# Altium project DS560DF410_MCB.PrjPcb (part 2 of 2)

## Sheet DF410_Egress_3.SchDoc: Retimer Egress RX1-4
size A2; Date: Not shown in title block; ApprovedBy: Not shown in title block; CheckedBy: Not shown in title block; Author: Not shown in title block; CompanyName: Not shown in title block; Engineer: Not shown in title block; Organization: Not shown in title block; Address1: Not shown in title block; Address2: Not shown in title block; Address3: Not shown in title block; Address4: Not shown in title block; DocumentNumber: 1; Revision: Use project parameter SCH_Rev; SheetNumber: 1; SheetTotal: 1; PageSetup: Record=PageOptions¦CenterHorizontal=True¦CenterVertical=True¦PrintScale=0.69¦XCorrection=1.00¦YCorrection=1.00¦PrintKind=0¦BorderSize=5000000¦LeftOffset=0¦BottomOffset=0¦Orientation=2¦PaperLength=1000¦PaperWidth=1000¦Scale=100¦PaperSource=15¦PrintQuality=600¦MediaType=1¦DitherType=10¦PaperKind=Letter¦PrintScaleMode=1
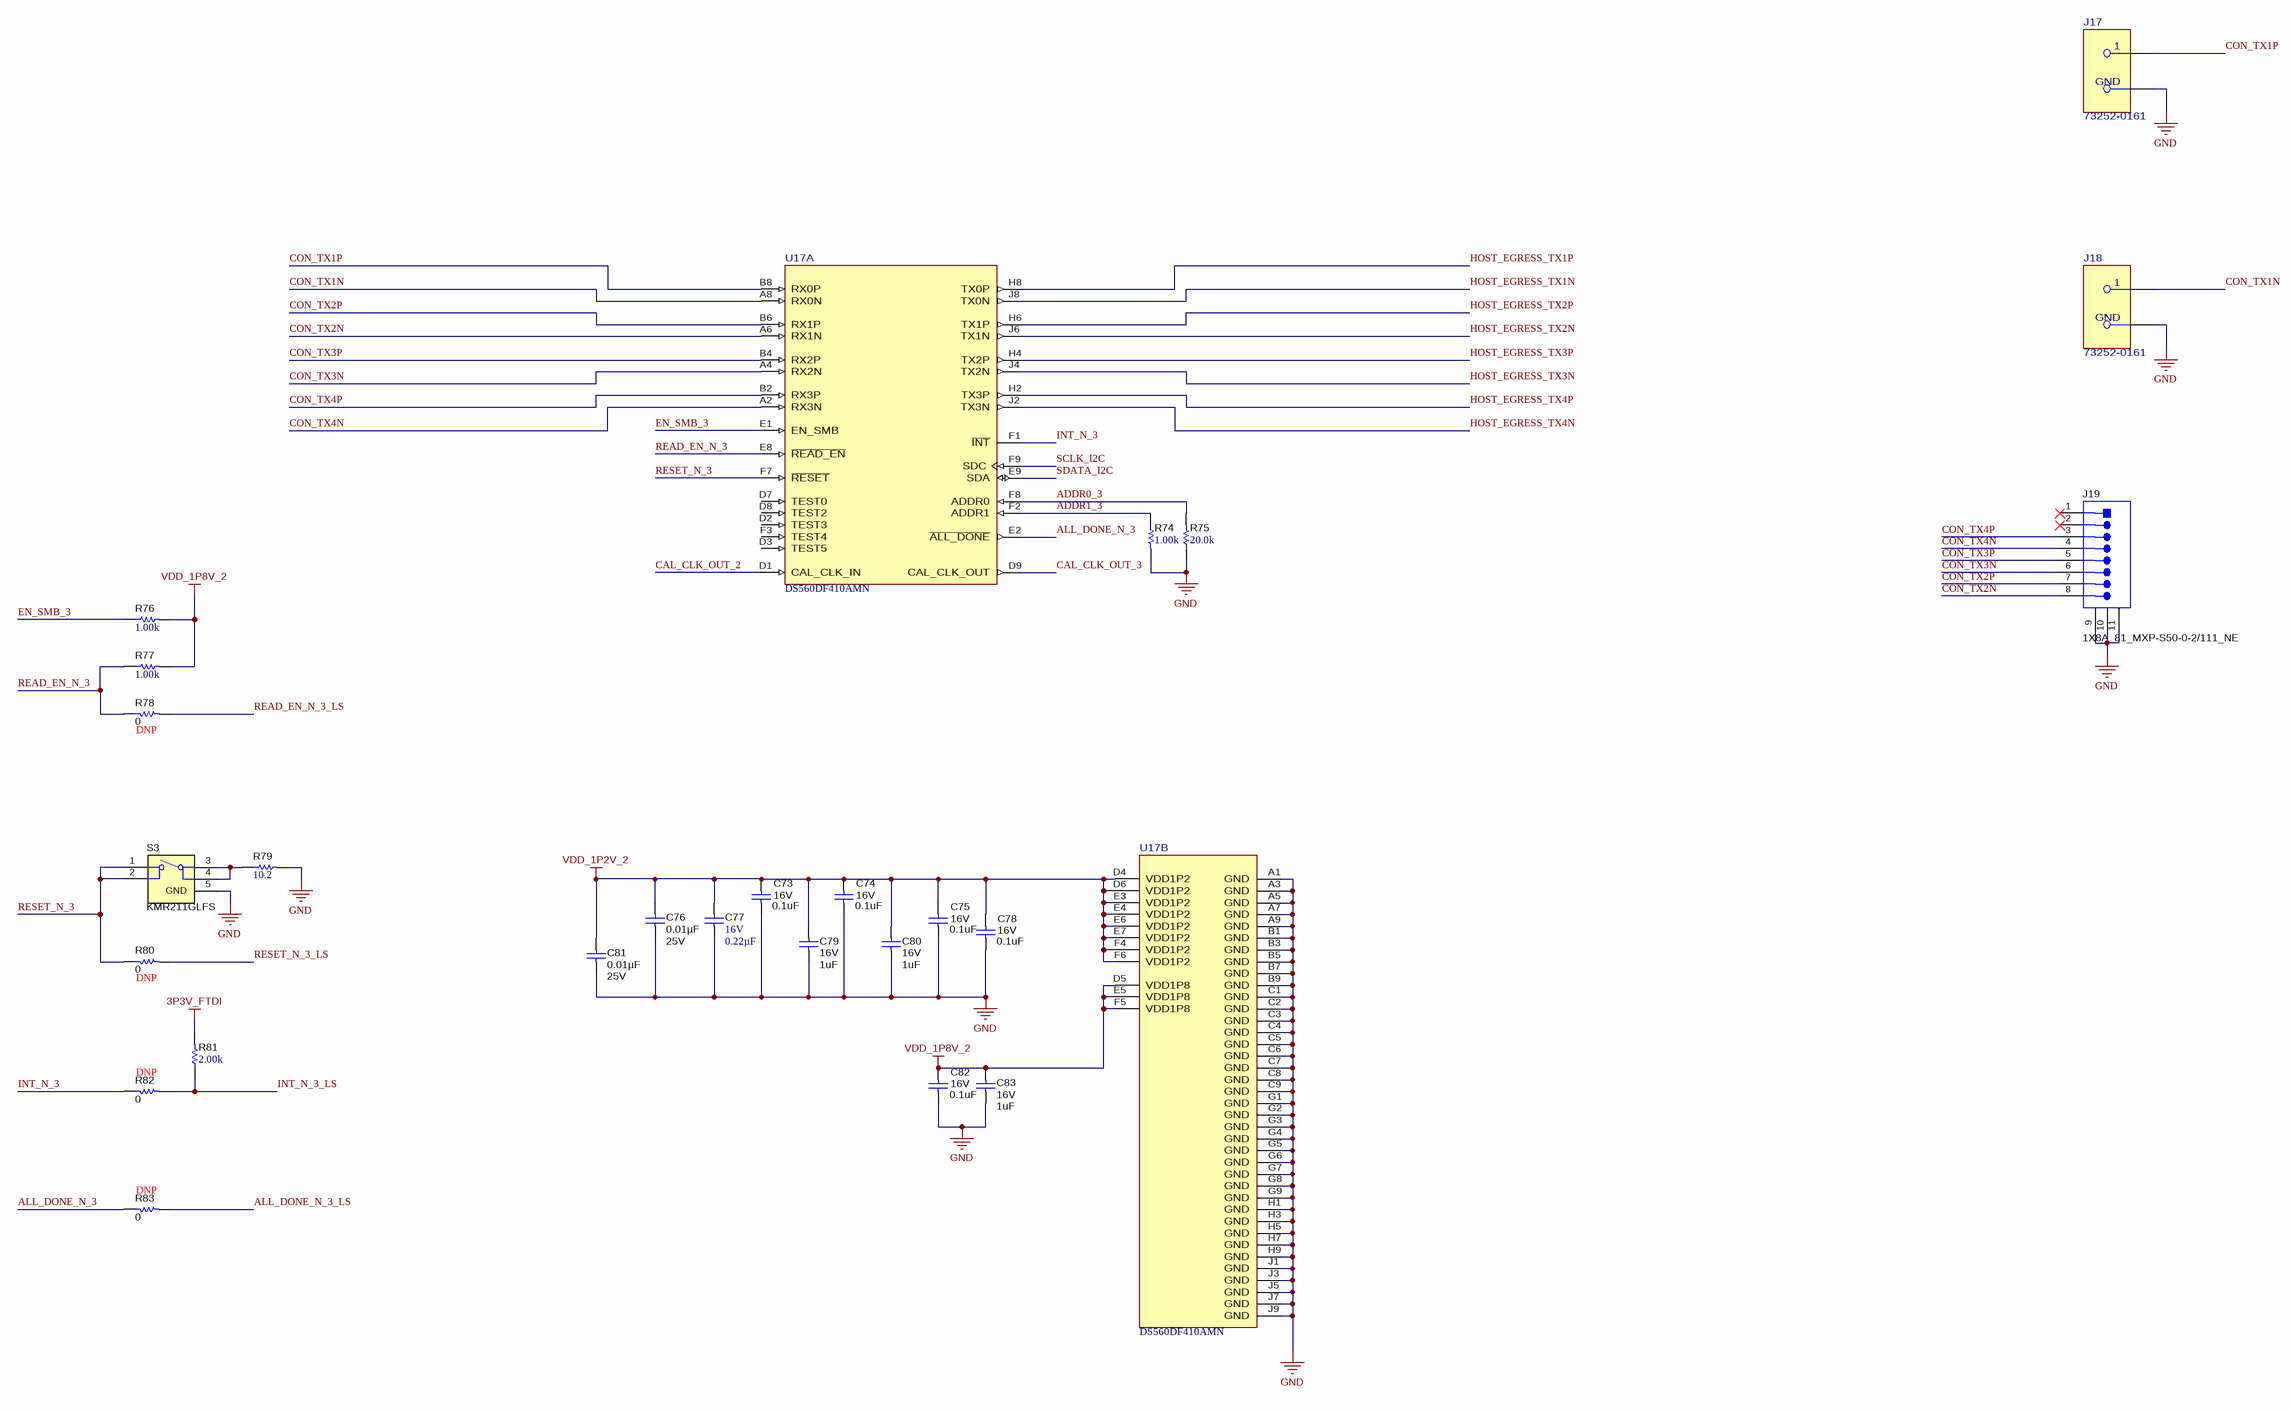
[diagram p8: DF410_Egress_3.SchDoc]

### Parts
C73  Value2: 16V  ValueDisplayed: 0.1uF  [0201_033]  (hidden comment: GRM033C71C104KE14D)
C74  Value2: 16V  ValueDisplayed: 0.1uF  [0201_033]  (hidden comment: GRM033C71C104KE14D)
C75  Value2: 16V  ValueDisplayed: 0.1uF  [0201_033]  (hidden comment: GRM033C71C104KE14D)
C76  ValueDisplayed: 0.01µF  VDC_V: 25V  [0201_033]  (hidden comment: GRM033R61E103KA12D)
C77  VDC_V: 16V  ValueDisplayed: 0.22µF  [0402]  (hidden comment: CL05B224KO5NNNC)
C78  Value2: 16V  ValueDisplayed: 0.1uF  [0201_033]  (hidden comment: GRM033C71C104KE14D)
C79  VDC_V: 16V  ValueDisplayed: 1uF  [0603]  (hidden comment: GRM188R61C105KA93D)
C80  VDC_V: 16V  ValueDisplayed: 1uF  [0603]  (hidden comment: GRM188R61C105KA93D)
C81  ValueDisplayed: 0.01µF  VDC_V: 25V  [0201_033]  (hidden comment: GRM033R61E103KA12D)
C82  Value2: 16V  ValueDisplayed: 0.1uF  [0201_033]  (hidden comment: GRM033C71C104KE14D)
C83  VDC_V: 16V  ValueDisplayed: 1uF  [0603]  (hidden comment: GRM188R61C105KA93D)
J17  73252-0161  [FP-73252-0161_CONN_RF_JACK-MFG]
J18  73252-0161  [FP-73252-0161_CONN_RF_JACK-MFG]
J19  1X8A_81_MXP-S50-0-2/111_NE  [H+S_1x8A_81_MXP-S50-0-2_111N]
R74  ValueDisplayed: 1.00k  [0402]  (hidden comment: CRCW04021K00FKED)
R75  ValueDisplayed: 20.0k  [0402]  (hidden comment: PCF0402-12-20K0BT1)
R76  ValueDisplayed: 1.00k  [0402]  (hidden comment: CRCW04021K00FKED)
R77  ValueDisplayed: 1.00k  [0402]  (hidden comment: CRCW04021K00FKED)
R78  ValueDisplayed: 0  [0402]  (hidden comment: ERJ-2GE0R00X)
R79  ValueDisplayed: 10.2  [0402]  (hidden comment: CRCW040210R2FKED)
R80  ValueDisplayed: 0  [0402]  (hidden comment: ERJ-2GE0R00X)
R81  ValueDisplayed: 2.00k  [0402]  (hidden comment: ERJ-2RKF2001X)
R82  ValueDisplayed: 0  [0402]  (hidden comment: ERJ-2GE0R00X)
R83  ValueDisplayed: 0  [0402]  (hidden comment: ERJ-2GE0R00X)
S3  KMR211GLFS  [SW_KMR211GLFS]
U17  DS560DF410AMN  [AMN0081A-MFG]  (parts A,B of 2)

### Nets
3P3V_FTDI: R81.2
GND: C73.2 C74.2 C75.2 C76.2 C77.2 C78.2 C79.2 C80.2 C81.2 C82.2 C83.2 J17.2(GND) J18.2(GND) J19.9 J19.10 J19.11 R74.2 R75.1 R79.2 S3.5(GND) U17.A1(GND) U17.A3(GND) U17.A5(GND) U17.A7(GND) U17.A9(GND) U17.B1(GND) U17.B3(GND) U17.B5(GND) U17.B7(GND) U17.B9(GND) U17.C1(GND) U17.C2(GND) U17.C3(GND) U17.C4(GND) U17.C5(GND) U17.C6(GND) U17.C7(GND) U17.C8(GND) U17.C9(GND) U17.G1(GND) U17.G2(GND) U17.G3(GND) U17.G4(GND) U17.G5(GND) U17.G6(GND) U17.G7(GND) U17.G8(GND) U17.G9(GND) U17.H1(GND) U17.H3(GND) U17.H5(GND) U17.H7(GND) U17.H9(GND) U17.J1(GND) U17.J3(GND) U17.J5(GND) U17.J7(GND) U17.J9(GND)
VDD_1P2V_2: C73.1 C74.1 C75.1 C76.1 C77.1 C78.1 C79.1 C80.1 C81.1 U17.D4(VDD1P2) U17.D6(VDD1P2) U17.E3(VDD1P2) U17.E4(VDD1P2) U17.E6(VDD1P2) U17.E7(VDD1P2) U17.F4(VDD1P2) U17.F6(VDD1P2)
VDD_1P8V_2: C82.1 C83.1 R76.2 R77.2 U17.D5(VDD1P8) U17.E5(VDD1P8) U17.F5(VDD1P8)
ADDR0_3: R75.2 U17.F8(ADDR0)
ADDR1_3: R74.1 U17.F2(ADDR1)
ALL_DONE_N_3: R83.1 U17.E2(~{ALL_DONE})
ALL_DONE_N_3_LS: R83.2
CAL_CLK_OUT_2: U17.D1(CAL_CLK_IN)
CAL_CLK_OUT_3: U17.D9(CAL_CLK_OUT)
CON_TX1N: J18.1 U17.A8(RX0N)
CON_TX1P: J17.1 U17.B8(RX0P)
CON_TX2N: J19.8 U17.A6(RX1N)
CON_TX2P: J19.7 U17.B6(RX1P)
CON_TX3N: J19.6 U17.A4(RX2N)
CON_TX3P: J19.5 U17.B4(RX2P)
CON_TX4N: J19.4 U17.A2(RX3N)
CON_TX4P: J19.3 U17.B2(RX3P)
EN_SMB_3: R76.1 U17.E1(EN_SMB)
HOST_EGRESS_TX1N: U17.J8(TX0N)
HOST_EGRESS_TX1P: U17.H8(TX0P)
HOST_EGRESS_TX2N: U17.J6(TX1N)
HOST_EGRESS_TX2P: U17.H6(TX1P)
HOST_EGRESS_TX3N: U17.J4(TX2N)
HOST_EGRESS_TX3P: U17.H4(TX2P)
HOST_EGRESS_TX4N: U17.J2(TX3N)
HOST_EGRESS_TX4P: U17.H2(TX3P)
INT_N_3: R82.1 U17.F1(~{INT})
INT_N_3_LS: R81.1 R82.2
READ_EN_N_3: R77.1 R78.1 U17.E8(~{READ_EN})
READ_EN_N_3_LS: R78.2
RESET_N_3: R80.1 S3.1 S3.2 U17.F7(~{RESET})
RESET_N_3_LS: R80.2
SCLK_I2C: U17.F9(SDC)
SDATA_I2C: U17.E9(SDA)
NetR79_1: R79.1 S3.3 S3.4

Not connected (* = marked no-connect by the designer): J19 1* 2*; U17 D2(TEST3) D3(TEST5) D7(TEST0) D8(TEST2) F3(TEST4)

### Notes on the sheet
- (near R78) DNP
- (near R80) DNP
- (near R82) DNP
- (near R83) DNP

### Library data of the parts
C73-C75 C78 C82 = CMP-0009670-3: CAP, CERM, 0.1 uF, 16 V, +/- 10%, X5R, 0201; Manufacturer: MuRata; TaMin_C: -55°C; Polarized: N; SizeAreaWB_mm2: 2.08; Value1: Unknown; U/M: EA; Value: 0.1uF; TaMax_C: 125°C; SizeZ_mm: 0.33; SizeX_mm: 0.6; SizeY_mm: 0.3; Cap_Case: 0201; SizeArea_mm2: 0.18; Cap_F: 100nF; AEC Category: Q200
C76 C81 = CMP-0086060-1: CAP, CERM, 0.01 µF, 25 V,+/- 10%, X5R, 0201; Manufacturer: MuRata; SizeY_mm: 0.3; SizeZ_mm: 0.33; SizeAreaWB_mm2: 2.08; U/M: EA; AEC Category: Q200; SizeX_mm: 0.6; TaMin_C: -55°C; Polarized: N; TaMax_C: 85°C; Value: 0.01uF; Cap_F: 10nF; SizeArea_mm2: 0.18; Cap_Case: 0201
C77 = CMP-0860563-1: CAP, CERM, 0.22 µF, 16 V,+/- 10%, X7R, 0402; Manufacturer: Samsung Electro-Mechanics; TaMin_C: -55°C; Polarized: N; SizeAreaWB_mm2: 3; U/M: EA; Value: 0.22uF; TaMax_C: 125°C; SizeZ_mm: 0.6; SizeX_mm: 1; SizeY_mm: 0.5; Cap_F: 220nF; AEC Category: Q200; Green_Lifecycle: Active; Green_REACh: Incomplete
C79 C80 C83 = CMP-0007335-5: CAP, CERM, 1 uF, 16 V, +/- 10%, X5R, 0603; Manufacturer: MuRata; TaMin_C: -55°C; Polarized: N; SizeAreaWB_mm2: 4.68; Value1: Unknown; U/M: EA; Value: 1uF; TaMax_C: 85°C; SizeZ_mm: 1; SizeX_mm: 1.6; SizeY_mm: 0.8; SizeArea_mm2: 1.28; Cap_F: 1µF; AEC Category: Q200
J17 J18 = CMP-0097248-1: 2.92MM JACK,PCB,COMPRESSION W/SL; Manufacturer: Molex; Is Female: yes; Conn Orientation: Vertical; Dielectric Material: PTFE; ContactFinish: Gold,Nickel; SizeZ_mm: 11.17mm; AEC Qualified: No
J19 = CMP-0074975-2: Straight PCB plug Pin-in-hole/SMT; Manufacturer: Huber+Suhner; CT: False; Green_REACh: Incomplete; Green_Lifecycle: Not Set
R74 R76 R77 = CMP-0026071-3: RES, 1.00 k, 1%, 0.063 W, AEC-Q200 Grade 0, 0402; Manufacturer: Vishay-Dale; Power_W: 63mW; TempCo: 100 ppm/C; Value_Code: 1k00; Value: 1.00k; EIA_Code: E96; Res_ohm: 1k; SizeX_mm: 1; SizeY_mm: 0.5; SizeZ_mm: 0.6; Value2: 0.063W; AEC Qualified: Y; VDC_V: 50V; AEC Category: Q200; AEC Grade: 0
R75 = CMP-0026801-1: RES, 20.0 k, 0.1%, 0.063 W, 0402; Manufacturer: TT Electronics/IRC; Power_W: 63mW; TempCo: 10 ppm/C; Value_Code: 20k0; U/M: EA; Value: 20.0k; EIA_Code: E192; Res_ohm: 20k; SizeX_mm: 1; SizeY_mm: 0.5; SizeZ_mm: 0.6; Value2: 0.063W; AEC Qualified: N; VDC_V: 25V; AEC Category: Q200
R78 R80 R82 R83 = CMP-0026992-3: RES, 0, 5%, 0.1 W, AEC-Q200 Grade 0, 0402; Manufacturer: Panasonic; Power_W: 100mW; TempCo: 600 ppm/C; Value_Code: 0000; Value: 0; EIA_Code: E24; SizeX_mm: 1; SizeY_mm: 0.5; SizeZ_mm: 0.6; Value2: 0.1W; AEC Qualified: Y; VDC_V: 50V; AEC Category: Q200; SizeAreaWB_mm2: 3
R79 = CMP-0025964-3: RES, 10.2, 1%, 0.063 W, AEC-Q200 Grade 0, 0402; Manufacturer: Vishay-Dale; Power_W: 63mW; TempCo: 100 ppm/C; Value_Code: 10R2; Value: 10.2; EIA_Code: E96; SizeX_mm: 1; SizeY_mm: 0.5; SizeZ_mm: 0.6; Value2: 0.063W; AEC Qualified: Y; VDC_V: 50V; AEC Category: Q200; AEC Grade: 0
R81 = CMP-0026676-1: RES, 2.00 k, 1%, 0.1 W, AEC-Q200 Grade 0, 0402; Manufacturer: Panasonic; Power_W: 100mW; TempCo: 100 ppm/C; Value_Code: 2k00; U/M: EA; Value: 2.00k; EIA_Code: E96; Res_ohm: 2k; SizeX_mm: 1; SizeY_mm: 0.5; SizeZ_mm: 0.6; Value2: 0.1W; AEC Qualified: Y; VDC_V: 50V; AEC Grade: 0; AEC Category: Q200
S3 = CMP-0002322-1: Switch, SPST-NO, Off-Mom, 0.05 A, 32 VDC, SMD; Manufacturer: C&K Components; CurrentRating_mA: 50A; PositionCount: 1; SizeX_mm: 4.6; SizeY_mm: 2.8; SizeZ_mm: 1.9; SizeArea_mm2: 12.88; VDC_V: 32V; SizeAreaWB_mm2: 21.28
U17 = CMP-0095008-2: 56 Gbps Multi-Rate 4-Channel Retimer with Crosspoint; Manufacturer: Texas Instruments; AEC Category: Q200; TaMin_C: -40°C; AEC Qualified: No; SizeZ_mm: 1.225mm; Standoff Height: 0.261mm; TJmax_C: +110°C; Data Rate: 56Gbits/s; Min Supply Voltage: 1.15V; Max Supply Voltage: 1.85V; CompType: IC; TaMax_C: +85°C; Interface: I2C,SMBus,Other

## Sheet DF410_Egress_4.SchDoc: Retimer Egress RX5-8
size A2; Date: Not shown in title block; ApprovedBy: Not shown in title block; CheckedBy: Not shown in title block; Author: Not shown in title block; CompanyName: Not shown in title block; Engineer: Not shown in title block; Organization: Not shown in title block; Address1: Not shown in title block; Address2: Not shown in title block; Address3: Not shown in title block; Address4: Not shown in title block; DocumentNumber: 1; Revision: Use project parameter SCH_Rev; SheetNumber: 1; SheetTotal: 1; PageSetup: Record=PageOptions¦CenterHorizontal=True¦CenterVertical=True¦PrintScale=0.69¦XCorrection=1.00¦YCorrection=1.00¦PrintKind=0¦BorderSize=5000000¦LeftOffset=0¦BottomOffset=0¦Orientation=2¦PaperLength=1000¦PaperWidth=1000¦Scale=100¦PaperSource=15¦PrintQuality=600¦MediaType=1¦DitherType=10¦PaperKind=Letter¦PrintScaleMode=1
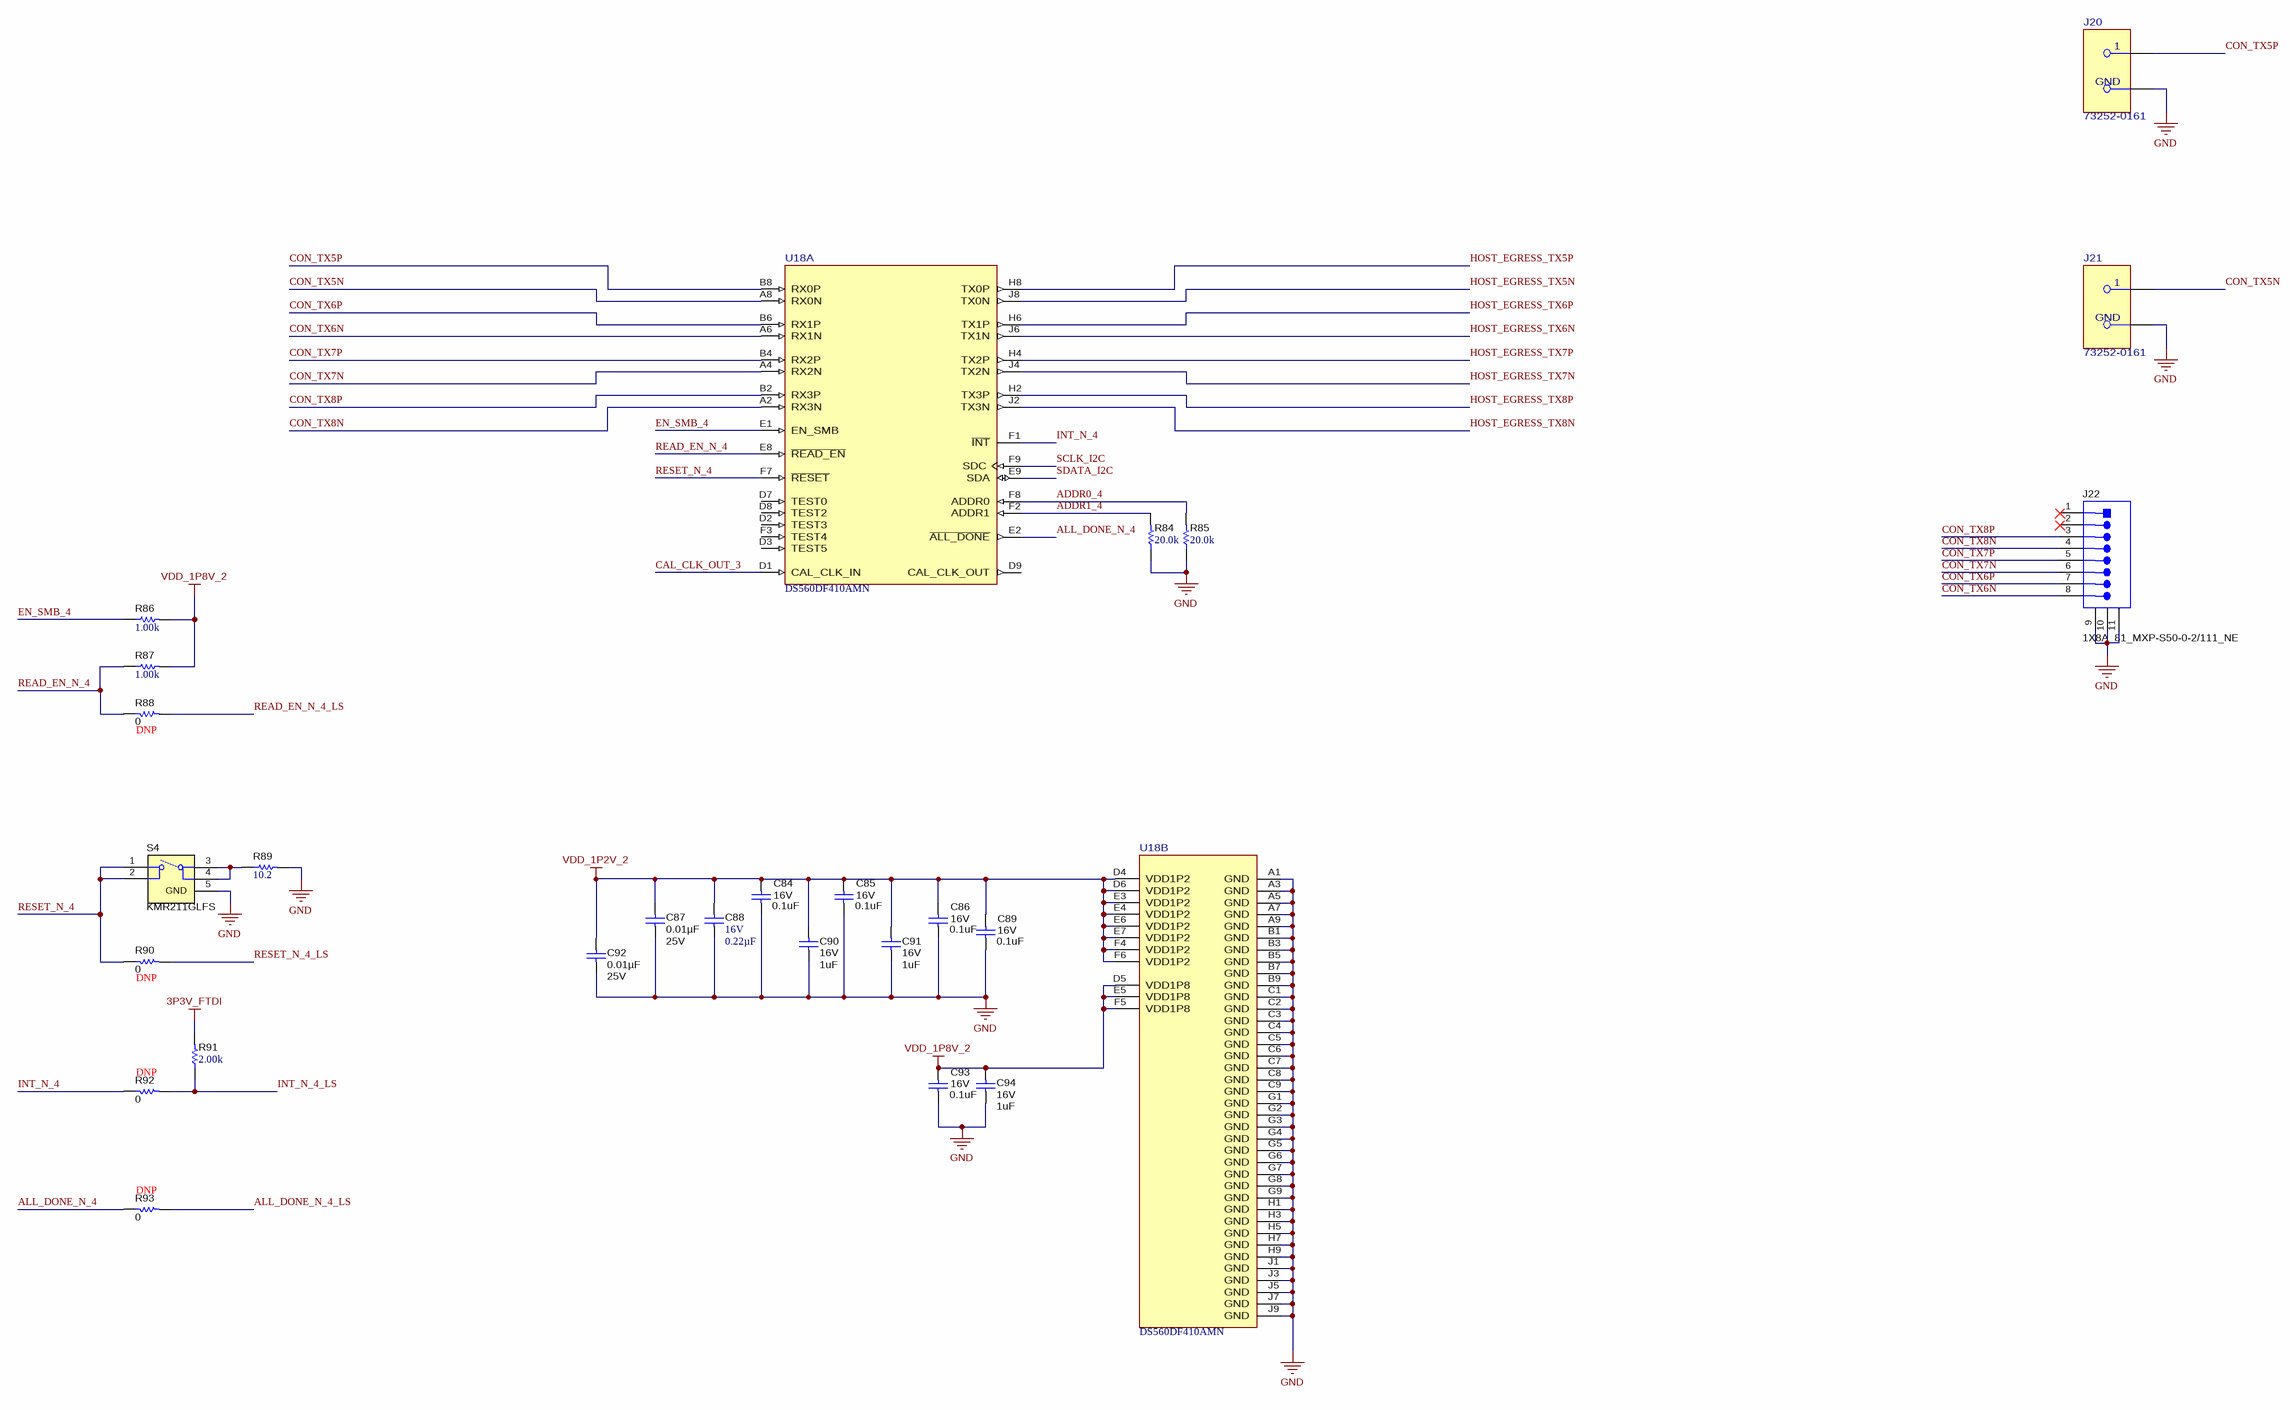
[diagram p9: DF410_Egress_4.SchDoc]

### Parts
C84  Value2: 16V  ValueDisplayed: 0.1uF  [0201_033]  (hidden comment: GRM033C71C104KE14D)
C85  Value2: 16V  ValueDisplayed: 0.1uF  [0201_033]  (hidden comment: GRM033C71C104KE14D)
C86  Value2: 16V  ValueDisplayed: 0.1uF  [0201_033]  (hidden comment: GRM033C71C104KE14D)
C87  ValueDisplayed: 0.01µF  VDC_V: 25V  [0201_033]  (hidden comment: GRM033R61E103KA12D)
C88  VDC_V: 16V  ValueDisplayed: 0.22µF  [0402]  (hidden comment: CL05B224KO5NNNC)
C89  Value2: 16V  ValueDisplayed: 0.1uF  [0201_033]  (hidden comment: GRM033C71C104KE14D)
C90  VDC_V: 16V  ValueDisplayed: 1uF  [0603]  (hidden comment: GRM188R61C105KA93D)
C91  VDC_V: 16V  ValueDisplayed: 1uF  [0603]  (hidden comment: GRM188R61C105KA93D)
C92  ValueDisplayed: 0.01µF  VDC_V: 25V  [0201_033]  (hidden comment: GRM033R61E103KA12D)
C93  Value2: 16V  ValueDisplayed: 0.1uF  [0201_033]  (hidden comment: GRM033C71C104KE14D)
C94  VDC_V: 16V  ValueDisplayed: 1uF  [0603]  (hidden comment: GRM188R61C105KA93D)
J20  73252-0161  [FP-73252-0161_CONN_RF_JACK-MFG]
J21  73252-0161  [FP-73252-0161_CONN_RF_JACK-MFG]
J22  1X8A_81_MXP-S50-0-2/111_NE  [H+S_1x8A_81_MXP-S50-0-2_111N]
R84  ValueDisplayed: 20.0k  [0402]  (hidden comment: PCF0402-12-20K0BT1)
R85  ValueDisplayed: 20.0k  [0402]  (hidden comment: PCF0402-12-20K0BT1)
R86  ValueDisplayed: 1.00k  [0402]  (hidden comment: CRCW04021K00FKED)
R87  ValueDisplayed: 1.00k  [0402]  (hidden comment: CRCW04021K00FKED)
R88  ValueDisplayed: 0  [0402]  (hidden comment: ERJ-2GE0R00X)
R89  ValueDisplayed: 10.2  [0402]  (hidden comment: CRCW040210R2FKED)
R90  ValueDisplayed: 0  [0402]  (hidden comment: ERJ-2GE0R00X)
R91  ValueDisplayed: 2.00k  [0402]  (hidden comment: ERJ-2RKF2001X)
R92  ValueDisplayed: 0  [0402]  (hidden comment: ERJ-2GE0R00X)
R93  ValueDisplayed: 0  [0402]  (hidden comment: ERJ-2GE0R00X)
S4  KMR211GLFS  [SW_KMR211GLFS]
U18  DS560DF410AMN  [AMN0081A-MFG]  (parts A,B of 2)

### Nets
3P3V_FTDI: R91.2
GND: C84.2 C85.2 C86.2 C87.2 C88.2 C89.2 C90.2 C91.2 C92.2 C93.2 C94.2 J20.2(GND) J21.2(GND) J22.9 J22.10 J22.11 R84.1 R85.1 R89.2 S4.5(GND) U18.A1(GND) U18.A3(GND) U18.A5(GND) U18.A7(GND) U18.A9(GND) U18.B1(GND) U18.B3(GND) U18.B5(GND) U18.B7(GND) U18.B9(GND) U18.C1(GND) U18.C2(GND) U18.C3(GND) U18.C4(GND) U18.C5(GND) U18.C6(GND) U18.C7(GND) U18.C8(GND) U18.C9(GND) U18.G1(GND) U18.G2(GND) U18.G3(GND) U18.G4(GND) U18.G5(GND) U18.G6(GND) U18.G7(GND) U18.G8(GND) U18.G9(GND) U18.H1(GND) U18.H3(GND) U18.H5(GND) U18.H7(GND) U18.H9(GND) U18.J1(GND) U18.J3(GND) U18.J5(GND) U18.J7(GND) U18.J9(GND)
VDD_1P2V_2: C84.1 C85.1 C86.1 C87.1 C88.1 C89.1 C90.1 C91.1 C92.1 U18.D4(VDD1P2) U18.D6(VDD1P2) U18.E3(VDD1P2) U18.E4(VDD1P2) U18.E6(VDD1P2) U18.E7(VDD1P2) U18.F4(VDD1P2) U18.F6(VDD1P2)
VDD_1P8V_2: C93.1 C94.1 R86.2 R87.2 U18.D5(VDD1P8) U18.E5(VDD1P8) U18.F5(VDD1P8)
ADDR0_4: R85.2 U18.F8(ADDR0)
ADDR1_4: R84.2 U18.F2(ADDR1)
ALL_DONE_N_4: R93.1 U18.E2(~{ALL_DONE})
ALL_DONE_N_4_LS: R93.2
CAL_CLK_OUT_3: U18.D1(CAL_CLK_IN)
CON_TX5N: J21.1 U18.A8(RX0N)
CON_TX5P: J20.1 U18.B8(RX0P)
CON_TX6N: J22.8 U18.A6(RX1N)
CON_TX6P: J22.7 U18.B6(RX1P)
CON_TX7N: J22.6 U18.A4(RX2N)
CON_TX7P: J22.5 U18.B4(RX2P)
CON_TX8N: J22.4 U18.A2(RX3N)
CON_TX8P: J22.3 U18.B2(RX3P)
EN_SMB_4: R86.1 U18.E1(EN_SMB)
HOST_EGRESS_TX5N: U18.J8(TX0N)
HOST_EGRESS_TX5P: U18.H8(TX0P)
HOST_EGRESS_TX6N: U18.J6(TX1N)
HOST_EGRESS_TX6P: U18.H6(TX1P)
HOST_EGRESS_TX7N: U18.J4(TX2N)
HOST_EGRESS_TX7P: U18.H4(TX2P)
HOST_EGRESS_TX8N: U18.J2(TX3N)
HOST_EGRESS_TX8P: U18.H2(TX3P)
INT_N_4: R92.1 U18.F1(~{INT})
INT_N_4_LS: R91.1 R92.2
READ_EN_N_4: R87.1 R88.1 U18.E8(~{READ_EN})
READ_EN_N_4_LS: R88.2
RESET_N_4: R90.1 S4.1 S4.2 U18.F7(~{RESET})
RESET_N_4_LS: R90.2
SCLK_I2C: U18.F9(SDC)
SDATA_I2C: U18.E9(SDA)
NetR89_1: R89.1 S4.3 S4.4

Not connected (* = marked no-connect by the designer): J22 1* 2*; U18 D2(TEST3) D3(TEST5) D7(TEST0) D8(TEST2) D9(CAL_CLK_OUT) F3(TEST4)

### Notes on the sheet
- (near R88) DNP
- (near R90) DNP
- (near R92) DNP
- (near R93) DNP

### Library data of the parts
C84-C86 C89 C93 = CMP-0009670-3: as C73-C75 on sheet DF410_Egress_3
C87 C92 = CMP-0086060-1: as C76 on sheet DF410_Egress_3
C88 = CMP-0860563-1: as C77 on sheet DF410_Egress_3
C90 C91 C94 = CMP-0007335-5: as C79 on sheet DF410_Egress_3
J20 J21 = CMP-0097248-1: as J17 on sheet DF410_Egress_3
J22 = CMP-0074975-2: as J19 on sheet DF410_Egress_3
R84 R85 = CMP-0026801-1: as R75 on sheet DF410_Egress_3
R86 R87 = CMP-0026071-3: as R74 on sheet DF410_Egress_3
R88 R90 R92 R93 = CMP-0026992-3: as R78 on sheet DF410_Egress_3
R89 = CMP-0025964-3: as R79 on sheet DF410_Egress_3
R91 = CMP-0026676-1: as R81 on sheet DF410_Egress_3
S4 = CMP-0002322-1: as S3 on sheet DF410_Egress_3
U18 = CMP-0095008-2: as U17 on sheet DF410_Egress_3

## Sheet QSFP-DD_Connector.SchDoc: QSFP-DD Connector
size 431 x 279 mm; Date: Not shown in title block; ApprovedBy: Not shown in title block; CheckedBy: Not shown in title block; Author: Not shown in title block; CompanyName: Not shown in title block; Engineer: Not shown in title block; Organization: Not shown in title block; Address1: Not shown in title block; Address2: Not shown in title block; Address3: Not shown in title block; Address4: Not shown in title block; DocumentNumber: 4; Revision: Use project parameter SCH_Rev; SheetNumber: 4; SheetTotal: 8; PageSetup: Record=PageOptions¦CenterHorizontal=True¦CenterVertical=True¦PrintScale=1.00¦XCorrection=1.00¦YCorrection=1.00¦PrintKind=0¦BorderSize=5000000¦LeftOffset=0¦BottomOffset=0¦Orientation=2¦PaperLength=1000¦PaperWidth=1000¦Scale=100¦PaperSource=15¦PrintQuality=600¦MediaType=1¦DitherType=10¦PaperKind=Letter¦PrintScaleMode=1
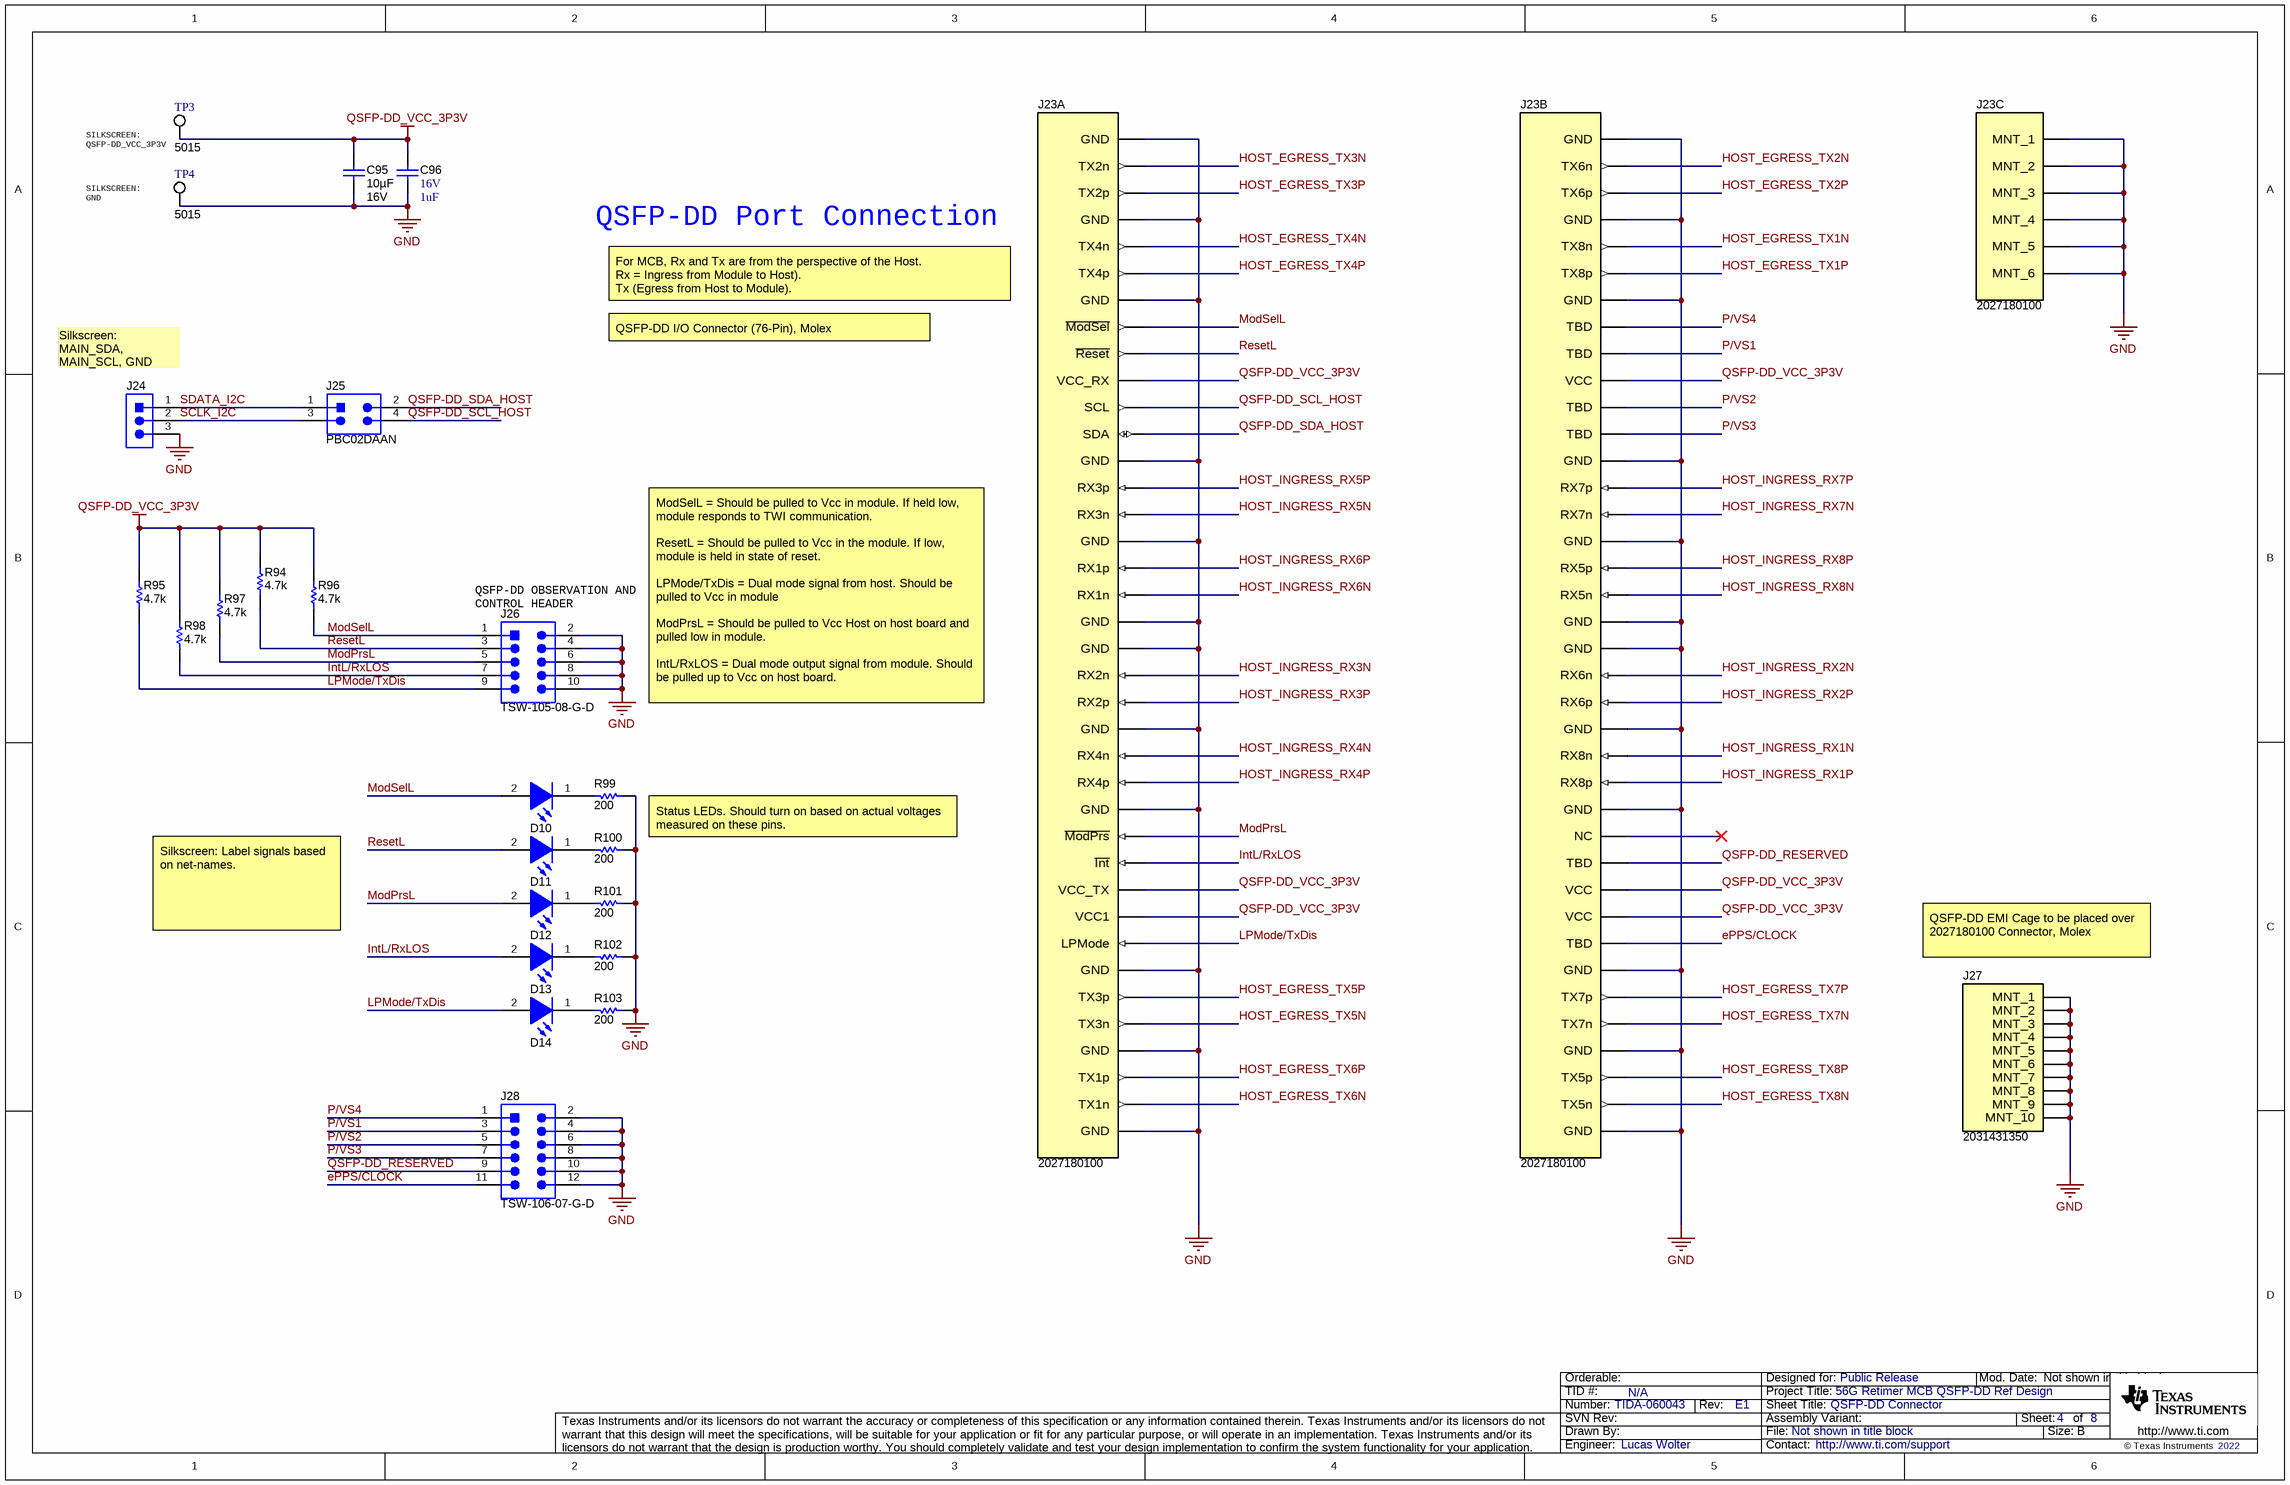
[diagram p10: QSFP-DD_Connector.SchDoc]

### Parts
C95  ValueDisplayed: 10µF  VDC_V: 16V  [0805_HV]  (hidden comment: GRM21BR61C106KE15K)
C96  VDC_V: 16V  ValueDisplayed: 1uF  [0603]  (hidden comment: GRM185R61C105KE44D)
D10  LG M67K-G1J2-24-Z  [LG_M67K_Green]  (value not drawn)
D11  LG M67K-G1J2-24-Z  [LG_M67K_Green]  (value not drawn)
D12  LG M67K-G1J2-24-Z  [LG_M67K_Green]  (value not drawn)
D13  LG M67K-G1J2-24-Z  [LG_M67K_Green]  (value not drawn)
D14  LG M67K-G1J2-24-Z  [LG_M67K_Green]  (value not drawn)
J23  2027180100  [FP-2027180100_HDR76-MFG]  (parts A,B,C of 3)
J24  TSW-103-08-G-S  [Samtec_TSW-103-08-x-S]  (value not drawn)
J25  PBC02DAAN  [Sullins_PxC02DAAN]
J26  TSW-105-08-G-D  [Samtec_TSW-105-08-x-D]
J27  2031431350  [FP-2031431350_CAGE_QSFP-DD-MFG]
J28  TSW-106-07-G-D  [TSW-106-07-G-D]
R94  ValueDisplayed: 4.7k  [0402]  (hidden comment: CRCW04024K70JNED)
R95  ValueDisplayed: 4.7k  [0402]  (hidden comment: CRCW04024K70JNED)
R96  ValueDisplayed: 4.7k  [0402]  (hidden comment: CRCW04024K70JNED)
R97  ValueDisplayed: 4.7k  [0402]  (hidden comment: CRCW04024K70JNED)
R98  ValueDisplayed: 4.7k  [0402]  (hidden comment: CRCW04024K70JNED)
R99  ValueDisplayed: 200  [0603]  (hidden comment: CRCW0603200RFKEA)
R100  ValueDisplayed: 200  [0603]  (hidden comment: CRCW0603200RFKEA)
R101  ValueDisplayed: 200  [0603]  (hidden comment: CRCW0603200RFKEA)
R102  ValueDisplayed: 200  [0603]  (hidden comment: CRCW0603200RFKEA)
R103  ValueDisplayed: 200  [0603]  (hidden comment: CRCW0603200RFKEA)
TP3  5015  [Testpoint_Keystone_Miniature]
TP4  5015  [Testpoint_Keystone_Miniature]

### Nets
GND: C95.2 C96.2 J23.1(GND) J23.4(GND) J23.7(GND) J23.13(GND) J23.16(GND) J23.19(GND) J23.20(GND) J23.23(GND) J23.26(GND) J23.32(GND) J23.35(GND) J23.38(GND) J23.39(GND) J23.42(GND) J23.45(GND) J23.51(GND) J23.54(GND) J23.57(GND) J23.58(GND) J23.61(GND) J23.64(GND) J23.70(GND) J23.73(GND) J23.76(GND) J23.77(MNT_1) J23.78(MNT_2) J23.79(MNT_3) J23.80(MNT_4) J23.81(MNT_5) J23.82(MNT_6) J24.3 J26.2 J26.4 J26.6 J26.8 J26.10 J27.1(MNT_1) J27.2(MNT_2) J27.3(MNT_3) J27.4(MNT_4) J27.5(MNT_5) J27.6(MNT_6) J27.7(MNT_7) J27.8(MNT_8) J27.9(MNT_9) J27.10(MNT_10) J28.2 J28.4 J28.6 J28.8 J28.10 J28.12 R99.1 R100.1 R101.1 R102.1 R103.1 TP4.1
QSFP-DD_VCC_3P3V: C95.1 C96.1 J23.10(VCC_RX) J23.29(VCC_TX) J23.30(VCC1) J23.48(VCC) J23.67(VCC) J23.68(VCC) R94.2 R95.2 R96.2 R97.2 R98.2 TP3.1
ePPS/CLOCK: J23.69(TBD) J28.11
HOST_EGRESS_TX1N: J23.43(TX8n)
HOST_EGRESS_TX1P: J23.44(TX8p)
HOST_EGRESS_TX2N: J23.40(TX6n)
HOST_EGRESS_TX2P: J23.41(TX6p)
HOST_EGRESS_TX3N: J23.2(TX2n)
HOST_EGRESS_TX3P: J23.3(TX2p)
HOST_EGRESS_TX4N: J23.5(TX4n)
HOST_EGRESS_TX4P: J23.6(TX4p)
HOST_EGRESS_TX5N: J23.34(TX3n)
HOST_EGRESS_TX5P: J23.33(TX3p)
HOST_EGRESS_TX6N: J23.37(TX1n)
HOST_EGRESS_TX6P: J23.36(TX1p)
HOST_EGRESS_TX7N: J23.72(TX7n)
HOST_EGRESS_TX7P: J23.71(TX7p)
HOST_EGRESS_TX8N: J23.75(TX5n)
HOST_EGRESS_TX8P: J23.74(TX5p)
HOST_INGRESS_RX1N: J23.62(RX8n)
HOST_INGRESS_RX1P: J23.63(RX8p)
HOST_INGRESS_RX2N: J23.59(RX6n)
HOST_INGRESS_RX2P: J23.60(RX6p)
HOST_INGRESS_RX3N: J23.21(RX2n)
HOST_INGRESS_RX3P: J23.22(RX2p)
HOST_INGRESS_RX4N: J23.24(RX4n)
HOST_INGRESS_RX4P: J23.25(RX4p)
HOST_INGRESS_RX5N: J23.15(RX3n)
HOST_INGRESS_RX5P: J23.14(RX3p)
HOST_INGRESS_RX6N: J23.18(RX1n)
HOST_INGRESS_RX6P: J23.17(RX1p)
HOST_INGRESS_RX7N: J23.53(RX7n)
HOST_INGRESS_RX7P: J23.52(RX7p)
HOST_INGRESS_RX8N: J23.56(RX5n)
HOST_INGRESS_RX8P: J23.55(RX5p)
IntL/RxLOS: D13.2(A) J23.28(~{Int}) J26.7 R98.1
LPMode/TxDis: D14.2(A) J23.31(LPMode) J26.9 R95.1
ModPrsL: D12.2(A) J23.27(~{ModPrs}) J26.5 R97.1
ModSelL: D10.2(A) J23.8(~{ModSel}) J26.1 R96.1
P/VS1: J23.47(TBD) J28.3
P/VS2: J23.49(TBD) J28.5
P/VS3: J23.50(TBD) J28.7
P/VS4: J23.46(TBD) J28.1
QSFP-DD_RESERVED: J23.66(TBD) J28.9
QSFP-DD_SCL_HOST: J23.11(SCL) J25.4
QSFP-DD_SDA_HOST: J23.12(SDA) J25.2
ResetL: D11.2(A) J23.9(~{Reset}) J26.3 R94.1
SCLK_I2C: J24.2 J25.3
SDATA_I2C: J24.1 J25.1
NetD10_1: D10.1(K) R99.2
NetD11_1: D11.1(K) R100.2
NetD12_1: D12.1(K) R101.2
NetD13_1: D13.1(K) R102.2
NetD14_1: D14.1(K) R103.2

Not connected (* = marked no-connect by the designer): J23 65(NC)*

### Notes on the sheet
- (near TP3) SILKSCREEN:
  QSFP-DD_VCC_3P3V
- (near TP4) SILKSCREEN:
  GND
- QSFP-DD Port Connection
- For MCB, Rx and Tx are from the perspective of the Host.
  Rx = Ingress from Module to Host).
  Tx (Egress from Host to Module).
- (near J24) Silkscreen: MAIN_SDA, MAIN_SCL, GND
- QSFP-DD I/O Connector (76-Pin), Molex
- (near J26) QSFP-DD OBSERVATION AND
  CONTROL HEADER
- ModSelL = Should be pulled to Vcc in module. If held low, module responds to TWI communication.
  ResetL = Should be pulled to Vcc in the module. If low, module is held in state of reset.
  LPMode/TxDis = Dual mode signal from host. Should be pulled to Vcc in module
  ModPrsL = Should be pulled to Vcc Host on host board and pulled low in module.
  IntL/RxLOS = Dual mode output signal from module. Should be pulled up to Vcc on host board.
- Status LEDs. Should turn on based on actual voltages measured on these pins.
- Silkscreen: Label signals based on net-names.
- (near J27) QSFP-DD EMI Cage to be placed over 2027180100 Connector, Molex

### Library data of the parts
C95 = CMP-0086228-1: CAP, CERM, 10 µF, 16 V,+/- 10%, X5R, 0805; Manufacturer: MuRata; Green_REACh: Incomplete; TaMax_C: 85°C; Value: 10uF; Green_Lifecycle: Active; AEC Qualified: N; SizeY_mm: 1.25; SizeX_mm: 2; AEC Category: Q200; Cap_Case: 0805; SizeArea_mm2: 2.5; SizeAreaWB_mm2: 6.75; SizeZ_mm: 1.45; TaMin_C: -55°C; U/M: EA
C96 = CMP-0007157-5: CAP, CERM, 1 uF, 16 V, +/- 10%, X5R, 0603; Manufacturer: MuRata; TaMin_C: -55°C; Polarized: N; SizeAreaWB_mm2: 4.68; Value1: Unknown; U/M: EA; Value: 1uF; TaMax_C: 85°C; SizeZ_mm: 1; SizeX_mm: 1.6; SizeY_mm: 0.8; SizeArea_mm2: 1.28; Cap_F: 1µF; AEC Category: Q200
D10-D14 = CMP-0002971-3: LED, Green, SMD; Manufacturer: OSRAM; Io_A: 2mA; Vr_V: 12V; Tjmax_C: 125°C; Value1: W; Angle: 120; Vf_V: 1.8V; Type: AlInGaP
J23 = CMP-0086993-2: 76 Position QSFP-DD (Double Density) Receptacle Connector Solder Surface Mount, Right Angle; Manufacturer: Molex; Current_A: 1A; Row_Count: 1; Voltage_V: 30V; ContactFinish: Gold,Nickel
J24 = CMP-0079327-1: Header, 2.54mm, 3x1, Gold, TH; Manufacturer: Samtec; Shrouded: N; Gender: Male; Row_Count: 1; Pitch_mm: 2.54; Cert_UL: Y
J25 = CMP-0054598-1: Header, 2.54mm, 2x2, Gold, TH; Manufacturer: Sullins Connector Solutions; CNHeader: TRUE; Current_A: 3A; Shrouded: N; Gender: Male; Voltage_V: 1.8kV; Row_Count: 2; RowSpacing_mm: 2.54; CT: FALSE; Cert_UL: Y
J26 = CMP-0860034-1: Header, 2.54mm, 5x2, Gold, TH; Manufacturer: Samtec; Pitch_mm: 2.54; Shrouded: N; Row_Count: 2; Cert_UL: Y; Gender: Male
J27 = CMP-0088065-1: Position QSFP-DD (Double Density) Cage with Heat Sink Connector Press-Fit Through Hole, Right Angle; Manufacturer: Molex; Shrouded: true
J28 = CMP-0075412-2: Header, 100mil, 6x2, Gold, TH; Manufacturer: Samtec; Pitch_mm: 2.54; Cert_VDE: N; Gender: Male; Cert_CSA: Y; Voltage_V: 550V; Green_REACh: Passed; Current_A: 6.3A; Green_Lifecycle: Active; Row_Count: 2
R94-R98 = CMP-0026938-5: RES, 4.7 k, 5%, 0.063 W, AEC-Q200 Grade 0, 0402; Manufacturer: Vishay-Dale; Power_W: 63mW; TempCo: 200 ppm/C; Value_Code: 4k70; Value: 4.7k; EIA_Code: E24; SizeX_mm: 1; SizeY_mm: 0.5; SizeZ_mm: 0.6; Value2: 0.063W; AEC Qualified: Y; VDC_V: 50V; AEC Category: Q200; AEC Grade: 0
R99-R103 = CMP-0022201-5: RES, 200, 1%, 0.1 W, AEC-Q200 Grade 0, 0603; Manufacturer: Vishay-Dale; Power_W: 100mW; TempCo: 100 ppm/C; Value_Code: 200R; Value: 200; EIA_Code: E96; SizeX_mm: 1.6; SizeY_mm: 0.8; SizeZ_mm: 1; Value2: 0.1W; SizeArea_mm2: 1.28; AEC Qualified: Y; VDC_V: 75V; AEC Category: Q200; AEC Grade: 0
TP3 TP4 = CMP-0055152-2: Test Point, Miniature, SMT; Manufacturer: Keystone Electronics; CNHeader: FALSE; Green_Lifecycle: Active; Green_REACh: Passed; CT: TRUE

## Sheet Hardware.SchDoc: PCB Hardware
size 431 x 279 mm; Date: Not shown in title block; ApprovedBy: Not shown in title block; CheckedBy: Not shown in title block; Author: Not shown in title block; CompanyName: Not shown in title block; Engineer: Not shown in title block; Organization: Not shown in title block; Address1: Not shown in title block; Address2: Not shown in title block; Address3: Not shown in title block; Address4: Not shown in title block; DocumentNumber: 8; Revision: Use project parameter SCH_Rev; SheetNumber: 8; SheetTotal: 8; PageSetup: Record=PageOptions¦CenterHorizontal=True¦CenterVertical=True¦PrintScale=1.00¦XCorrection=1.00¦YCorrection=1.00¦PrintKind=0¦BorderSize=5000000¦LeftOffset=0¦BottomOffset=0¦Orientation=2¦PaperLength=1000¦PaperWidth=1000¦Scale=100¦PaperSource=15¦PrintQuality=600¦MediaType=1¦DitherType=10¦PaperKind=Letter¦PrintScaleMode=1
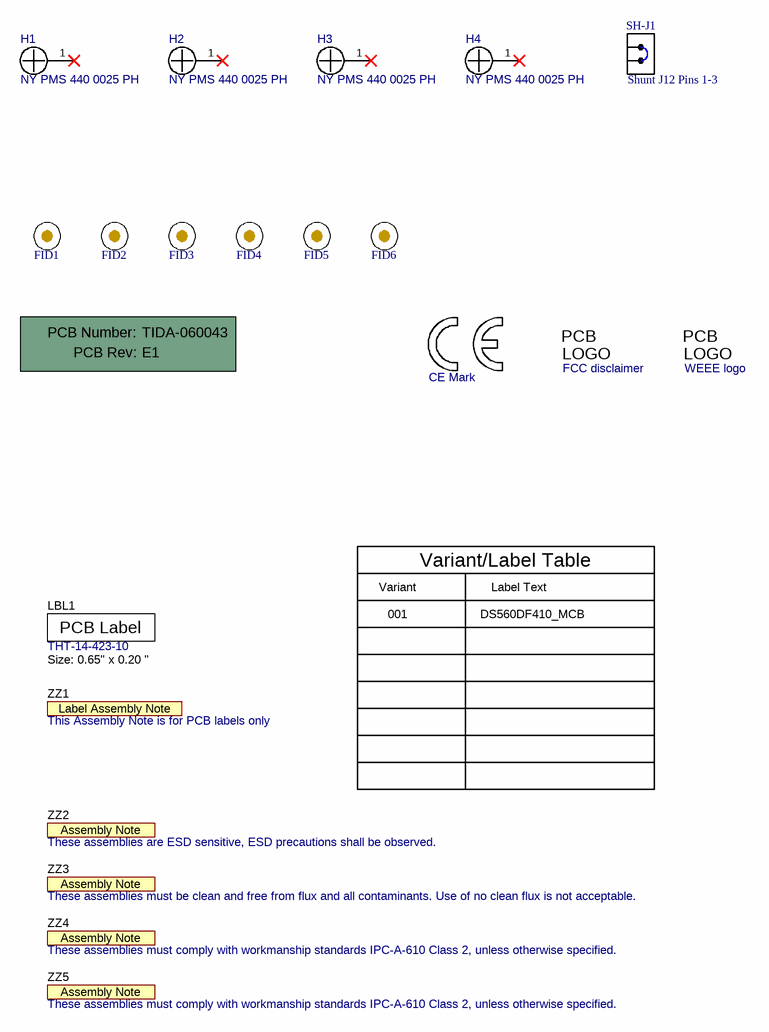
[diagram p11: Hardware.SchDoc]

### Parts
!PCB1  Printed Circuit Board  (value not drawn)  (mechanical)
FID1  Fiducial  [Fiducial10-30]  (value not drawn)
FID2  Fiducial  [Fiducial10-30]  (value not drawn)
FID3  Fiducial  [Fiducial10-30]  (value not drawn)
FID4  Fiducial  [Fiducial10-30]  (value not drawn)
FID5  Fiducial  [Fiducial10-30]  (value not drawn)
FID6  Fiducial  [Fiducial10-30]  (value not drawn)
H1  NY PMS 440 0025 PH  [NY PMS 440 0025 PH]
H2  NY PMS 440 0025 PH  [NY PMS 440 0025 PH]
H3  NY PMS 440 0025 PH  [NY PMS 440 0025 PH]
H4  NY PMS 440 0025 PH  [NY PMS 440 0025 PH]
LBL1  THT-14-423-10  Note: Size: 0.65" x 0.20 "  [Label_650x200]
Logo1  CE Mark  [CE_Mark_5mm]  (no BOM)
Logo3  FCC disclaimer  [FCC_disclaimer]  (no BOM)
Logo4  WEEE logo  [WEEE_Minimum]  (no BOM)
SH-J1  SPC02SYAN  [SPC02SYAN]  (value not drawn)
ZZ1  This Assembly Note is for PCB labels only  [AssemblyNoteLabel]  (no BOM)
ZZ2  These assemblies are ESD sensitive, ESD precautions shall be observed.  [AssemblyNote]  (no BOM)
ZZ3  These assemblies must be clean and free from flux and all contaminants. Use of no clean flux is not acceptable.  [AssemblyNote]  (no BOM)
ZZ4  These assemblies must comply with workmanship standards IPC-A-610 Class 2, unless otherwise specified.  [AssemblyNote]  (no BOM)
ZZ5  These assemblies must comply with workmanship standards IPC-A-610 Class 2, unless otherwise specified.  [AssemblyNote]  (no BOM)

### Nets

Not connected (* = marked no-connect by the designer): H1 1*; H2 1*; H3 1*; H4 1*

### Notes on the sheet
- (near SH-J1) Shunt J12 Pins 1-3
- Variant
- Variant/Label Table
- Label Text
- 001
- DS560DF410_MCB

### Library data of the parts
!PCB1 = CMP-0003618-2: Manufacturer: Any; PartNumber: TIDA-060043
FID1-FID6 = CMP-0077181-1: Fiducial mark.  There is nothing to buy or mount.
H1-H4 = CMP-0003617-1: Machine Screw, Round, #4-40 x 1/4, Nylon, Philips panhead; Manufacturer: B&F Fastener Supply; CompType: Hardware
LBL1 = CMP-0003625-1: Thermal Transfer Printable Labels, 0.650" W x 0.200" H - 10,000 per roll; Manufacturer: Brady
Logo1 = CMP-0074844-1: SymbolCreator: a0412235
Logo3 = CMP-0074847-1: FCC_disclaimer
Logo4 = CMP-0074769-1
SH-J1 = CMP-0003642-1: Shunt, 100mil, Flash Gold, Black; Manufacturer: Sullins Connector Solutions; Value: 1x2; Note: You can "mate" this to a header by matching the designator.  i.e. use SH-J3 for header J3
ZZ1 = CMP-0003616-3
ZZ2 = CMP-0077236-1
ZZ3 = CMP-0077237-1
ZZ4 ZZ5 = CMP-0077238-1

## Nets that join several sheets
3P3V_FTDI: FTDI_USB (21 pins), DF410_Ingress_1 (R61.2), DF410_Ingress_2 (R71.2), DF410_Egress_3 (R81.2), DF410_Egress_4 (R91.2)
GND: FTDI_USB (48 pins), PWR_Supplies (66 pins), DF410_Ingress_1 (64 pins), DF410_Ingress_2 (58 pins), DF410_Egress_3 (58 pins), DF410_Egress_4 (58 pins), QSFP-DD_Connector (60 pins)
VDD_1P2V_1: PWR_Supplies (U7.3), DF410_Ingress_1 (17 pins), DF410_Ingress_2 (17 pins)
VDD_1P2V_2: PWR_Supplies (U9.3), DF410_Egress_3 (17 pins), DF410_Egress_4 (17 pins)
VDD_1P8V_1: FTDI_USB (C9.1 U2.2 U2.10), PWR_Supplies (R43.1 U12.3), DF410_Ingress_1 (10 pins), DF410_Ingress_2 (7 pins)
VDD_1P8V_2: FTDI_USB (C13.2 U4.2 U4.10), PWR_Supplies (R51.1 U14.3), DF410_Egress_3 (7 pins), DF410_Egress_4 (7 pins)
ALL_DONE_N_1_LS: FTDI_USB (U2.5), DF410_Ingress_1 (R63.2)
ALL_DONE_N_2_LS: FTDI_USB (U2.9), DF410_Ingress_2 (R73.2)
ALL_DONE_N_3_LS: FTDI_USB (U4.5), DF410_Egress_3 (R83.2)
ALL_DONE_N_4_LS: FTDI_USB (U4.9), DF410_Egress_4 (R93.2)
CAL_CLK_OUT_1: DF410_Ingress_1 (U15.D9), DF410_Ingress_2 (U16.D1)
CAL_CLK_OUT_2: DF410_Ingress_2 (U16.D9), DF410_Egress_3 (U17.D1)
CAL_CLK_OUT_3: DF410_Egress_3 (U17.D9), DF410_Egress_4 (U18.D1)
HOST_EGRESS_TX1N: DF410_Egress_3 (U17.J8), QSFP-DD_Connector (J23.43)
HOST_EGRESS_TX1P: DF410_Egress_3 (U17.H8), QSFP-DD_Connector (J23.44)
HOST_EGRESS_TX2N: DF410_Egress_3 (U17.J6), QSFP-DD_Connector (J23.40)
HOST_EGRESS_TX2P: DF410_Egress_3 (U17.H6), QSFP-DD_Connector (J23.41)
HOST_EGRESS_TX3N: DF410_Egress_3 (U17.J4), QSFP-DD_Connector (J23.2)
HOST_EGRESS_TX3P: DF410_Egress_3 (U17.H4), QSFP-DD_Connector (J23.3)
HOST_EGRESS_TX4N: DF410_Egress_3 (U17.J2), QSFP-DD_Connector (J23.5)
HOST_EGRESS_TX4P: DF410_Egress_3 (U17.H2), QSFP-DD_Connector (J23.6)
HOST_EGRESS_TX5N: DF410_Egress_4 (U18.J8), QSFP-DD_Connector (J23.34)
HOST_EGRESS_TX5P: DF410_Egress_4 (U18.H8), QSFP-DD_Connector (J23.33)
HOST_EGRESS_TX6N: DF410_Egress_4 (U18.J6), QSFP-DD_Connector (J23.37)
HOST_EGRESS_TX6P: DF410_Egress_4 (U18.H6), QSFP-DD_Connector (J23.36)
HOST_EGRESS_TX7N: DF410_Egress_4 (U18.J4), QSFP-DD_Connector (J23.72)
HOST_EGRESS_TX7P: DF410_Egress_4 (U18.H4), QSFP-DD_Connector (J23.71)
HOST_EGRESS_TX8N: DF410_Egress_4 (U18.J2), QSFP-DD_Connector (J23.75)
HOST_EGRESS_TX8P: DF410_Egress_4 (U18.H2), QSFP-DD_Connector (J23.74)
HOST_INGRESS_RX1N: DF410_Ingress_1 (U15.A8), QSFP-DD_Connector (J23.62)
HOST_INGRESS_RX1P: DF410_Ingress_1 (U15.B8), QSFP-DD_Connector (J23.63)
HOST_INGRESS_RX2N: DF410_Ingress_1 (U15.A6), QSFP-DD_Connector (J23.59)
HOST_INGRESS_RX2P: DF410_Ingress_1 (U15.B6), QSFP-DD_Connector (J23.60)
HOST_INGRESS_RX3N: DF410_Ingress_1 (U15.A4), QSFP-DD_Connector (J23.21)
HOST_INGRESS_RX3P: DF410_Ingress_1 (U15.B4), QSFP-DD_Connector (J23.22)
HOST_INGRESS_RX4N: DF410_Ingress_1 (U15.A2), QSFP-DD_Connector (J23.24)
HOST_INGRESS_RX4P: DF410_Ingress_1 (U15.B2), QSFP-DD_Connector (J23.25)
HOST_INGRESS_RX5N: DF410_Ingress_2 (U16.A8), QSFP-DD_Connector (J23.15)
HOST_INGRESS_RX5P: DF410_Ingress_2 (U16.B8), QSFP-DD_Connector (J23.14)
HOST_INGRESS_RX6N: DF410_Ingress_2 (U16.A6), QSFP-DD_Connector (J23.18)
HOST_INGRESS_RX6P: DF410_Ingress_2 (U16.B6), QSFP-DD_Connector (J23.17)
HOST_INGRESS_RX7N: DF410_Ingress_2 (U16.A4), QSFP-DD_Connector (J23.53)
HOST_INGRESS_RX7P: DF410_Ingress_2 (U16.B4), QSFP-DD_Connector (J23.52)
HOST_INGRESS_RX8N: DF410_Ingress_2 (U16.A2), QSFP-DD_Connector (J23.56)
HOST_INGRESS_RX8P: DF410_Ingress_2 (U16.B2), QSFP-DD_Connector (J23.55)
INT_N_1_LS: FTDI_USB (U2.4), DF410_Ingress_1 (R61.1 R62.2)
INT_N_2_LS: FTDI_USB (U2.8), DF410_Ingress_2 (R71.1 R72.2)
INT_N_3_LS: FTDI_USB (U4.4), DF410_Egress_3 (R81.1 R82.2)
INT_N_4_LS: FTDI_USB (U4.8), DF410_Egress_4 (R91.1 R92.2)
READ_EN_N_1_LS: FTDI_USB (U2.1), DF410_Ingress_1 (R56.2)
READ_EN_N_2_LS: FTDI_USB (U2.6), DF410_Ingress_2 (R68.2)
READ_EN_N_3_LS: FTDI_USB (U4.1), DF410_Egress_3 (R78.2)
READ_EN_N_4_LS: FTDI_USB (U4.6), DF410_Egress_4 (R88.2)
RESET_N_1_LS: FTDI_USB (U2.3), DF410_Ingress_1 (R59.2)
RESET_N_2_LS: FTDI_USB (U2.7), DF410_Ingress_2 (R70.2)
RESET_N_3_LS: FTDI_USB (U4.3), DF410_Egress_3 (R80.2)
RESET_N_4_LS: FTDI_USB (U4.7), DF410_Egress_4 (R90.2)
SCLK_I2C: FTDI_USB (R1.1 R2.1), DF410_Ingress_1 (U15.F9), DF410_Ingress_2 (U16.F9), DF410_Egress_3 (U17.F9), DF410_Egress_4 (U18.F9), QSFP-DD_Connector (J24.2 J25.3)
SDATA_I2C: FTDI_USB (R3.1 R5.1), DF410_Ingress_1 (U15.E9), DF410_Ingress_2 (U16.E9), DF410_Egress_3 (U17.E9), DF410_Egress_4 (U18.E9), QSFP-DD_Connector (J24.1 J25.1)

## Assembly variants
001: not fitted C18 R16 R21 R22 R31 R36 R39 R44 R47 R56 R59 R62 R63 R68 R70 R72 R73 R78 R80 R82 R83 R88 R90 R92 R93 TP1 TP2 TP3 TP4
